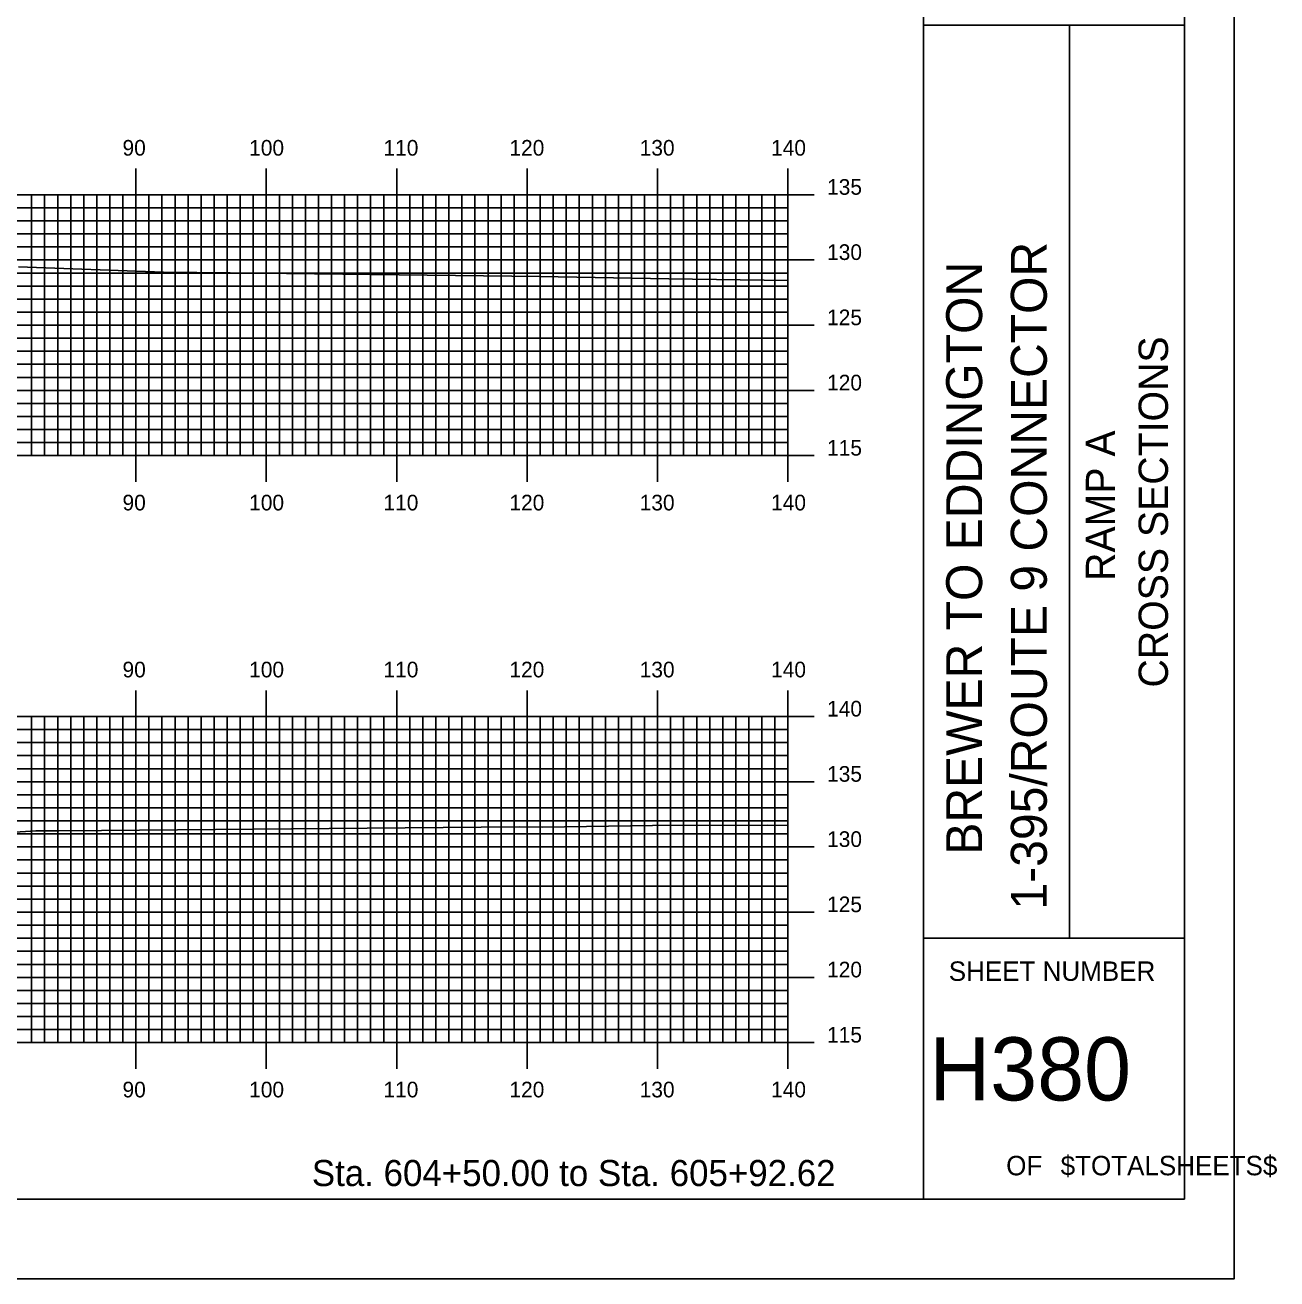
# Model space of a CAD drawing. Extents: x 842175 to 842518, y 363538 to 363758.
# Drawn here: x 842422.4 to 842518.4, y 363537.6 to 363633.7 of the extents above; entities that cross this region are included whole.
import ezdxf

# ---------------------------------------------------------------- set-up
doc = ezdxf.new("R2010")
doc.units = 0
for name, color, linetype in [('BORDER', 7, 'Continuous'), ('H_V ANNOTATION', 7, 'Continuous'), ('MAJOR', 7, 'Continuous'), ('MINOR', 7, 'Continuous'), ('PLOT BOUNDARY', 7, 'Continuous'), ('S_Roadway_Centerline', 7, 'Continuous')]:
    doc.layers.add(name, color=color, linetype=linetype)

msp = doc.modelspace()

# ---------------------------------------------------------------- linework, layer by layer
at = {"layer": 'BORDER'}
for p, q in [((842491.285, 363543.721), (842491.285, 363753.721)), ((842491.285, 363633.727), (842511.285, 363633.727)), ((842502.467, 363563.727), (842502.467, 363633.727)), ((842491.285, 363563.727), (842511.285, 363563.727))]:
    msp.add_line(p, q, dxfattribs=at)
msp.add_lwpolyline([(842191.285, 363543.721), (842511.285, 363543.721), (842511.285, 363753.721), (842191.285, 363753.721)], close=True, dxfattribs=at)
at = {"layer": 'MAJOR'}
for p, q in [((842430.885, 363622.725), (842430.885, 363620.721)), ((842440.885, 363622.725), (842440.885, 363620.721)), ((842450.885, 363622.725), (842450.885, 363620.721)), ((842460.885, 363622.725), (842460.885, 363620.721)), ((842470.885, 363622.725), (842470.885, 363620.721)), ((842480.885, 363622.725), (842480.885, 363620.721)), ((842200.885, 363620.721), (842480.885, 363620.721)), ((842200.885, 363620.721), (842480.885, 363620.721)), ((842430.885, 363600.721), (842430.885, 363620.721)), ((842440.885, 363600.721), (842440.885, 363620.721)), ((842450.885, 363600.721), (842450.885, 363620.721)), ((842460.885, 363600.721), (842460.885, 363620.721)), ((842470.885, 363600.721), (842470.885, 363620.721)), ((842482.889, 363620.721), (842478.881, 363620.721)), ((842480.885, 363600.721), (842480.885, 363620.721)), ((842480.885, 363600.721), (842480.885, 363620.721)), ((842200.885, 363615.721), (842480.885, 363615.721)), ((842482.889, 363615.721), (842478.881, 363615.721)), ((842200.885, 363610.721), (842480.885, 363610.721)), ((842482.889, 363610.721), (842478.881, 363610.721)), ((842200.885, 363605.721), (842480.885, 363605.721)), ((842482.889, 363605.721), (842478.881, 363605.721)), ((842200.885, 363600.721), (842480.885, 363600.721)), ((842200.885, 363600.721), (842480.885, 363600.721)), ((842430.885, 363598.717), (842430.885, 363600.721)), ((842440.885, 363598.717), (842440.885, 363600.721)), ((842450.885, 363598.717), (842450.885, 363600.721)), ((842460.885, 363598.717), (842460.885, 363600.721)), ((842470.885, 363598.717), (842470.885, 363600.721)), ((842482.889, 363600.721), (842478.881, 363600.721)), ((842480.885, 363598.717), (842480.885, 363600.721)), ((842430.885, 363582.725), (842430.885, 363580.721)), ((842440.885, 363582.725), (842440.885, 363580.721)), ((842450.885, 363582.725), (842450.885, 363580.721)), ((842460.885, 363582.725), (842460.885, 363580.721)), ((842470.885, 363582.725), (842470.885, 363580.721)), ((842480.885, 363582.725), (842480.885, 363580.721)), ((842200.885, 363580.721), (842480.885, 363580.721)), ((842200.885, 363580.721), (842480.885, 363580.721)), ((842430.885, 363555.721), (842430.885, 363580.721)), ((842440.885, 363555.721), (842440.885, 363580.721)), ((842450.885, 363555.721), (842450.885, 363580.721)), ((842460.885, 363555.721), (842460.885, 363580.721)), ((842470.885, 363555.721), (842470.885, 363580.721)), ((842482.889, 363580.721), (842478.881, 363580.721)), ((842480.885, 363555.721), (842480.885, 363580.721)), ((842480.885, 363555.721), (842480.885, 363580.721)), ((842200.885, 363575.721), (842480.885, 363575.721)), ((842482.889, 363575.721), (842478.881, 363575.721)), ((842200.885, 363570.721), (842480.885, 363570.721)), ((842482.889, 363570.721), (842478.881, 363570.721)), ((842200.885, 363565.721), (842480.885, 363565.721)), ((842482.889, 363565.721), (842478.881, 363565.721)), ((842200.885, 363560.721), (842480.885, 363560.721)), ((842482.889, 363560.721), (842478.881, 363560.721)), ((842200.885, 363555.721), (842480.885, 363555.721)), ((842200.885, 363555.721), (842480.885, 363555.721)), ((842430.885, 363553.717), (842430.885, 363555.721)), ((842440.885, 363553.717), (842440.885, 363555.721)), ((842450.885, 363553.717), (842450.885, 363555.721)), ((842460.885, 363553.717), (842460.885, 363555.721)), ((842470.885, 363553.717), (842470.885, 363555.721)), ((842482.889, 363555.721), (842478.881, 363555.721)), ((842480.885, 363553.717), (842480.885, 363555.721))]:
    msp.add_line(p, q, dxfattribs=at)
at = {"layer": 'MINOR'}
for p, q in [((842422.885, 363600.721), (842422.885, 363620.721)), ((842423.885, 363600.721), (842423.885, 363620.721)), ((842424.885, 363600.721), (842424.885, 363620.721)), ((842425.885, 363600.721), (842425.885, 363620.721)), ((842426.885, 363600.721), (842426.885, 363620.721)), ((842427.885, 363600.721), (842427.885, 363620.721)), ((842428.885, 363600.721), (842428.885, 363620.721)), ((842429.885, 363600.721), (842429.885, 363620.721)), ((842431.885, 363600.721), (842431.885, 363620.721)), ((842432.885, 363600.721), (842432.885, 363620.721)), ((842433.885, 363600.721), (842433.885, 363620.721)), ((842434.885, 363600.721), (842434.885, 363620.721)), ((842435.885, 363600.721), (842435.885, 363620.721)), ((842436.885, 363600.721), (842436.885, 363620.721)), ((842437.885, 363600.721), (842437.885, 363620.721)), ((842438.885, 363600.721), (842438.885, 363620.721)), ((842439.885, 363600.721), (842439.885, 363620.721)), ((842441.885, 363600.721), (842441.885, 363620.721)), ((842442.885, 363600.721), (842442.885, 363620.721)), ((842443.885, 363600.721), (842443.885, 363620.721)), ((842444.885, 363600.721), (842444.885, 363620.721)), ((842445.885, 363600.721), (842445.885, 363620.721)), ((842446.885, 363600.721), (842446.885, 363620.721)), ((842447.885, 363600.721), (842447.885, 363620.721)), ((842448.885, 363600.721), (842448.885, 363620.721)), ((842449.885, 363600.721), (842449.885, 363620.721)), ((842451.885, 363600.721), (842451.885, 363620.721)), ((842452.885, 363600.721), (842452.885, 363620.721)), ((842453.885, 363600.721), (842453.885, 363620.721)), ((842454.885, 363600.721), (842454.885, 363620.721)), ((842455.885, 363600.721), (842455.885, 363620.721)), ((842456.885, 363600.721), (842456.885, 363620.721)), ((842457.885, 363600.721), (842457.885, 363620.721)), ((842458.885, 363600.721), (842458.885, 363620.721)), ((842459.885, 363600.721), (842459.885, 363620.721)), ((842461.885, 363600.721), (842461.885, 363620.721)), ((842462.885, 363600.721), (842462.885, 363620.721)), ((842463.885, 363600.721), (842463.885, 363620.721)), ((842464.885, 363600.721), (842464.885, 363620.721)), ((842465.885, 363600.721), (842465.885, 363620.721)), ((842466.885, 363600.721), (842466.885, 363620.721)), ((842467.885, 363600.721), (842467.885, 363620.721)), ((842468.885, 363600.721), (842468.885, 363620.721)), ((842469.885, 363600.721), (842469.885, 363620.721)), ((842471.885, 363600.721), (842471.885, 363620.721)), ((842472.885, 363600.721), (842472.885, 363620.721)), ((842473.885, 363600.721), (842473.885, 363620.721)), ((842474.885, 363600.721), (842474.885, 363620.721)), ((842475.885, 363600.721), (842475.885, 363620.721)), ((842476.885, 363600.721), (842476.885, 363620.721)), ((842477.885, 363600.721), (842477.885, 363620.721)), ((842478.885, 363600.721), (842478.885, 363620.721)), ((842479.885, 363600.721), (842479.885, 363620.721)), ((842200.885, 363619.721), (842480.885, 363619.721)), ((842480.885, 363619.721), (842478.881, 363619.721)), ((842200.885, 363618.721), (842480.885, 363618.721)), ((842480.885, 363618.721), (842478.881, 363618.721)), ((842200.885, 363617.721), (842480.885, 363617.721)), ((842480.885, 363617.721), (842478.881, 363617.721)), ((842200.885, 363616.721), (842480.885, 363616.721)), ((842480.885, 363616.721), (842478.881, 363616.721)), ((842200.885, 363614.721), (842480.885, 363614.721)), ((842480.885, 363614.721), (842478.881, 363614.721)), ((842200.885, 363613.721), (842480.885, 363613.721)), ((842480.885, 363613.721), (842478.881, 363613.721)), ((842200.885, 363612.721), (842480.885, 363612.721)), ((842480.885, 363612.721), (842478.881, 363612.721)), ((842200.885, 363611.721), (842480.885, 363611.721)), ((842480.885, 363611.721), (842478.881, 363611.721)), ((842200.885, 363609.721), (842480.885, 363609.721)), ((842480.885, 363609.721), (842478.881, 363609.721)), ((842200.885, 363608.721), (842480.885, 363608.721)), ((842480.885, 363608.721), (842478.881, 363608.721)), ((842200.885, 363607.721), (842480.885, 363607.721)), ((842480.885, 363607.721), (842478.881, 363607.721)), ((842200.885, 363606.721), (842480.885, 363606.721)), ((842480.885, 363606.721), (842478.881, 363606.721)), ((842200.885, 363604.721), (842480.885, 363604.721)), ((842480.885, 363604.721), (842478.881, 363604.721)), ((842200.885, 363603.721), (842480.885, 363603.721)), ((842480.885, 363603.721), (842478.881, 363603.721)), ((842200.885, 363602.721), (842480.885, 363602.721)), ((842480.885, 363602.721), (842478.881, 363602.721)), ((842200.885, 363601.721), (842480.885, 363601.721)), ((842480.885, 363601.721), (842478.881, 363601.721)), ((842422.885, 363555.721), (842422.885, 363580.721)), ((842423.885, 363555.721), (842423.885, 363580.721)), ((842424.885, 363555.721), (842424.885, 363580.721)), ((842425.885, 363555.721), (842425.885, 363580.721)), ((842426.885, 363555.721), (842426.885, 363580.721)), ((842427.885, 363555.721), (842427.885, 363580.721)), ((842428.885, 363555.721), (842428.885, 363580.721)), ((842429.885, 363555.721), (842429.885, 363580.721)), ((842431.885, 363555.721), (842431.885, 363580.721)), ((842432.885, 363555.721), (842432.885, 363580.721)), ((842433.885, 363555.721), (842433.885, 363580.721)), ((842434.885, 363555.721), (842434.885, 363580.721)), ((842435.885, 363555.721), (842435.885, 363580.721)), ((842436.885, 363555.721), (842436.885, 363580.721)), ((842437.885, 363555.721), (842437.885, 363580.721)), ((842438.885, 363555.721), (842438.885, 363580.721)), ((842439.885, 363555.721), (842439.885, 363580.721)), ((842441.885, 363555.721), (842441.885, 363580.721)), ((842442.885, 363555.721), (842442.885, 363580.721)), ((842443.885, 363555.721), (842443.885, 363580.721)), ((842444.885, 363555.721), (842444.885, 363580.721)), ((842445.885, 363555.721), (842445.885, 363580.721)), ((842446.885, 363555.721), (842446.885, 363580.721)), ((842447.885, 363555.721), (842447.885, 363580.721)), ((842448.885, 363555.721), (842448.885, 363580.721)), ((842449.885, 363555.721), (842449.885, 363580.721)), ((842451.885, 363555.721), (842451.885, 363580.721)), ((842452.885, 363555.721), (842452.885, 363580.721)), ((842453.885, 363555.721), (842453.885, 363580.721)), ((842454.885, 363555.721), (842454.885, 363580.721)), ((842455.885, 363555.721), (842455.885, 363580.721)), ((842456.885, 363555.721), (842456.885, 363580.721)), ((842457.885, 363555.721), (842457.885, 363580.721)), ((842458.885, 363555.721), (842458.885, 363580.721)), ((842459.885, 363555.721), (842459.885, 363580.721)), ((842461.885, 363555.721), (842461.885, 363580.721)), ((842462.885, 363555.721), (842462.885, 363580.721)), ((842463.885, 363555.721), (842463.885, 363580.721)), ((842464.885, 363555.721), (842464.885, 363580.721)), ((842465.885, 363555.721), (842465.885, 363580.721)), ((842466.885, 363555.721), (842466.885, 363580.721)), ((842467.885, 363555.721), (842467.885, 363580.721)), ((842468.885, 363555.721), (842468.885, 363580.721)), ((842469.885, 363555.721), (842469.885, 363580.721)), ((842471.885, 363555.721), (842471.885, 363580.721)), ((842472.885, 363555.721), (842472.885, 363580.721)), ((842473.885, 363555.721), (842473.885, 363580.721)), ((842474.885, 363555.721), (842474.885, 363580.721)), ((842475.885, 363555.721), (842475.885, 363580.721)), ((842476.885, 363555.721), (842476.885, 363580.721)), ((842477.885, 363555.721), (842477.885, 363580.721)), ((842478.885, 363555.721), (842478.885, 363580.721)), ((842479.885, 363555.721), (842479.885, 363580.721)), ((842200.885, 363579.721), (842480.885, 363579.721)), ((842480.885, 363579.721), (842478.881, 363579.721)), ((842200.885, 363578.721), (842480.885, 363578.721)), ((842480.885, 363578.721), (842478.881, 363578.721)), ((842200.885, 363577.721), (842480.885, 363577.721)), ((842480.885, 363577.721), (842478.881, 363577.721)), ((842200.885, 363576.721), (842480.885, 363576.721)), ((842480.885, 363576.721), (842478.881, 363576.721)), ((842200.885, 363574.721), (842480.885, 363574.721)), ((842480.885, 363574.721), (842478.881, 363574.721)), ((842200.885, 363573.721), (842480.885, 363573.721)), ((842480.885, 363573.721), (842478.881, 363573.721)), ((842200.885, 363572.721), (842480.885, 363572.721)), ((842480.885, 363572.721), (842478.881, 363572.721)), ((842200.885, 363571.721), (842480.885, 363571.721)), ((842480.885, 363571.721), (842478.881, 363571.721)), ((842200.885, 363569.721), (842480.885, 363569.721)), ((842480.885, 363569.721), (842478.881, 363569.721)), ((842200.885, 363568.721), (842480.885, 363568.721)), ((842480.885, 363568.721), (842478.881, 363568.721)), ((842200.885, 363567.721), (842480.885, 363567.721)), ((842480.885, 363567.721), (842478.881, 363567.721)), ((842200.885, 363566.721), (842480.885, 363566.721)), ((842480.885, 363566.721), (842478.881, 363566.721)), ((842200.885, 363564.721), (842480.885, 363564.721)), ((842480.885, 363564.721), (842478.881, 363564.721)), ((842200.885, 363563.721), (842480.885, 363563.721)), ((842480.885, 363563.721), (842478.881, 363563.721)), ((842200.885, 363562.721), (842480.885, 363562.721)), ((842480.885, 363562.721), (842478.881, 363562.721)), ((842200.885, 363561.721), (842480.885, 363561.721)), ((842480.885, 363561.721), (842478.881, 363561.721)), ((842200.885, 363559.721), (842480.885, 363559.721)), ((842480.885, 363559.721), (842478.881, 363559.721)), ((842200.885, 363558.721), (842480.885, 363558.721)), ((842480.885, 363558.721), (842478.881, 363558.721)), ((842200.885, 363557.721), (842480.885, 363557.721)), ((842480.885, 363557.721), (842478.881, 363557.721)), ((842200.885, 363556.721), (842480.885, 363556.721)), ((842480.885, 363556.721), (842478.881, 363556.721))]:
    msp.add_line(p, q, dxfattribs=at)
at = {"layer": 'PLOT BOUNDARY'}
msp.add_lwpolyline([(842175.098, 363537.603), (842515.098, 363537.603), (842515.098, 363757.603), (842175.098, 363757.603)], close=True, dxfattribs=at)
at = {"layer": 'S_Roadway_Centerline'}
for points in [[(842421.873, 363615.203), (842432.992, 363614.789), (842438.103, 363614.733), (842461.871, 363614.46), (842471.763, 363614.264), (842480.885, 363614.139)], [(842417.157, 363571.568), (842423.219, 363571.957), (842424.97, 363571.954), (842428.255, 363571.983), (842460.276, 363572.268), (842462.051, 363572.229), (842470.503, 363572.353), (842479.301, 363572.393), (842480.885, 363572.353)]]:
    msp.add_lwpolyline(points, dxfattribs=at)

# ---------------------------------------------------------------- texts
at = {"layer": 'BORDER'}
for s, height, p in [('1-395/ROUTE 9 CONNECTOR', 2.75575, (842500.734, 363565.921)), ('BREWER TO EDDINGTON', 2.75575, (842495.774, 363570.13)), ('CROSS SECTIONS', 2.25, (842510.026, 363582.943)), ('RAMP A', 2.25, (842505.976, 363591.118))]:
    msp.add_text(s, height=height, rotation=90, dxfattribs=at).set_placement(p)
for s, height, p in [('SHEET NUMBER', 1.49054, (842493.216, 363560.454)), ('H380', 4.8388, (842491.724, 363551.286)), ('OF', 1.4905, (842497.619, 363545.547)), ('$TOTALSHEETS$', 1.49054, (842501.798, 363545.547))]:
    msp.add_text(s, height=height, dxfattribs=at).set_placement(p)
at = {"layer": 'H_V ANNOTATION'}
for s, height, p in [('90', 1.2, (842429.857, 363623.721)), ('100', 1.2, (842439.568, 363623.721)), ('110', 1.2, (842449.868, 363623.721)), ('120', 1.2, (842459.526, 363623.721)), ('130', 1.2, (842469.515, 363623.721)), ('140', 1.2, (842479.59, 363623.721)), ('135', 1.2, (842483.885, 363620.721)), ('130', 1.2, (842483.885, 363615.721)), ('125', 1.2, (842483.885, 363610.721)), ('120', 1.2, (842483.885, 363605.721)), ('115', 1.2, (842483.885, 363600.721)), ('90', 1.2, (842429.857, 363596.521)), ('100', 1.2, (842439.568, 363596.521)), ('110', 1.2, (842449.868, 363596.521)), ('120', 1.2, (842459.526, 363596.521)), ('130', 1.2, (842469.515, 363596.521)), ('140', 1.2, (842479.59, 363596.521)), ('90', 1.2, (842429.857, 363583.721)), ('100', 1.2, (842439.568, 363583.721)), ('110', 1.2, (842449.868, 363583.721)), ('120', 1.2, (842459.526, 363583.721)), ('130', 1.2, (842469.515, 363583.721)), ('140', 1.2, (842479.59, 363583.721)), ('140', 1.2, (842483.885, 363580.721)), ('135', 1.2, (842483.885, 363575.721)), ('130', 1.2, (842483.885, 363570.721)), ('125', 1.2, (842483.885, 363565.721)), ('120', 1.2, (842483.885, 363560.721)), ('115', 1.2, (842483.885, 363555.721)), ('90', 1.2, (842429.857, 363551.521)), ('100', 1.2, (842439.568, 363551.521)), ('110', 1.2, (842449.868, 363551.521)), ('120', 1.2, (842459.526, 363551.521)), ('130', 1.2, (842469.515, 363551.521)), ('140', 1.2, (842479.59, 363551.521)), ('Sta. 604+50.00 to Sta. 605+92.62', 2.0004, (842444.376, 363544.721))]:
    msp.add_text(s, height=height, dxfattribs=at).set_placement(p)

doc.saveas('drawing.dxf')
